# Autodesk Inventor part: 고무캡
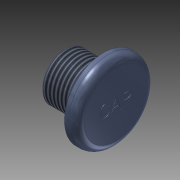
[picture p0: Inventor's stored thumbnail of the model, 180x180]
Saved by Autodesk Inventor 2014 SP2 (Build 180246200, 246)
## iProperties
Created: 2017-06
Part Number: 고무캡
Material: 고무
Document SubType Name: Modeling
Designer: mduedu
Density: 1 g/cm^3
Appearance: 고무 - 파란색 - 버전 1.1
Author: mduedu
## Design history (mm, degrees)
sketch "스케치1"
  geometry: L1 (0, 0)-(13, 0); L2 (13, 0)-(13, 10); L3 (13, 10)-(10, 10); L4 (0, 6)-(0, 0); L5 (0, 6)-(8, 6); L6 (8, 6)-(8, 8); L7 (8, 8)-(10, 8); L8 (10, 8)-(10, 10)
  constraints: 16 end point, 2 horizontal, 2 parallel, 2 perpendicular, 2 point on line, 1 vertical
  dimensions: "d0" = 20 diameter of L3 L1; "d2" = 12 diameter of L5 L1; "d6" = 5 distance between parallel lines of L2 L6; "d8" = 16 diameter of L7 L1; "d9" = 8 distance between parallel lines of L6 L4; "d32" = 2 distance of L6.end L7.end
revolve "회전1" sketch "스케치1" stored, may be unused: angle "d10" = 90 deg
hole "구멍1" diameter "d22" = 5; stored, may be unused: countersink angle "d26" = 90 deg, drill point angle "d28" = 0 deg; dims "d23" = 6, "d24" = 4, "d25" = 2, "d27" = 6, "d30" = 10, "d31" = 10
chamfer "모따기1" distance "d13" = 0.5; stored, may be unused: second distance "d14" = 2, angle "d15" = 45 deg
fillet "모깎기3" dims "d29" = 1
fillet "모깎기2" dims "d17" = 2
sketch "스케치3"
  geometry: 2 further points
  constraints: 1 coincident, 1 other
feature "엠보싱1" sketch "스케치3" dims "d18" = 0.2, "d19" = 0, "d29" = 1
feature "스레드1" dims "d33" = 10, "d34" = 0
node "솔리드1"
